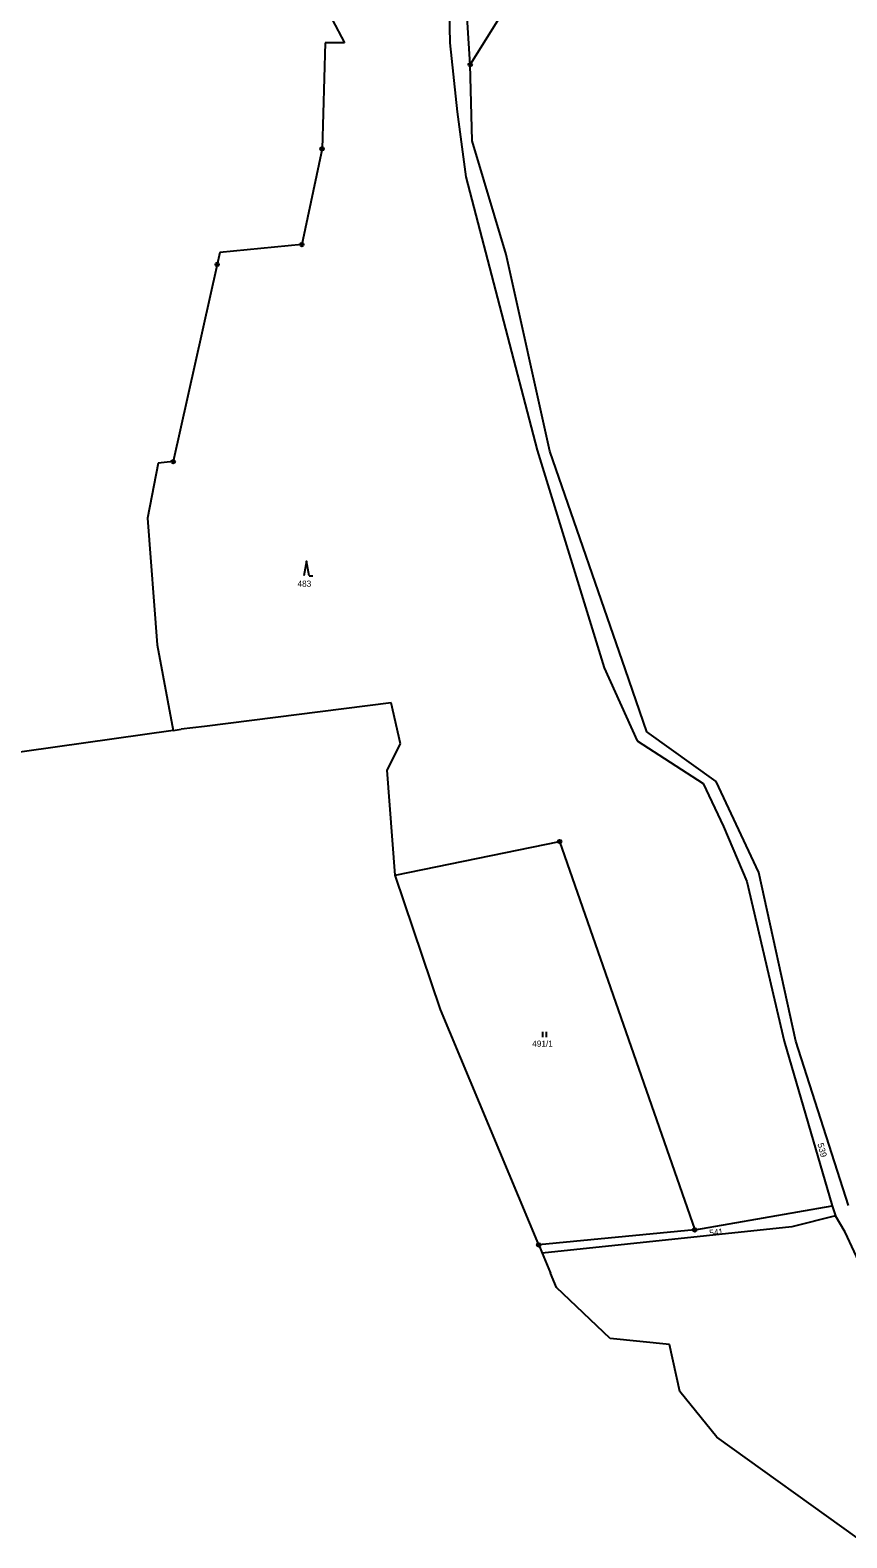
# Model space of a CAD drawing. Extents: x -885985 to -883535, y -1030025 to -1027941.
# Drawn here: x -884769.9 to -884544.6, y -1029741.6 to -1029325.6 of the extents above; entities that cross this region are included whole.
import ezdxf

# ---------------------------------------------------------------- set-up
doc = ezdxf.new("R2010")
doc.units = 0
doc.header["$LTSCALE"] = 0.68
for name, color, linetype, lineweight in [('1', 7, 'Continuous', 25), ('3', 7, 'Continuous', 25), ('8', 7, 'Continuous', 25)]:
    doc.layers.add(name, color=color, linetype=linetype, lineweight=lineweight)
doc.layers.add('2', color=7, linetype='Continuous')

msp = doc.modelspace()

# ---------------------------------------------------------------- linework, layer by layer
at = {"layer": '1'}
for p, q in [((-884648.51, -1029335.14), (-884651.18, -1029291.98)), ((-884654.72, -1029297.17), (-884654.13, -1029329.15)), ((-884693.78, -1029309.03), (-884683.21, -1029329.13)), ((-884640.06, -1029321.63), (-884648.51, -1029335.14)), ((-884688.49, -1029329.15), (-884689.38, -1029358.36)), ((-884683.21, -1029329.13), (-884688.49, -1029329.15)), ((-884654.13, -1029329.15), (-884652.07, -1029348.15)), ((-884647.96, -1029356.14), (-884648.51, -1029335.14)), ((-884652.07, -1029348.15), (-884649.72, -1029366.05)), ((-884638.56, -1029387.53), (-884647.96, -1029356.14)), ((-884689.38, -1029358.36), (-884694.96, -1029384.78)), ((-884649.72, -1029366.05), (-884630.04, -1029441.51)), ((-884694.96, -1029384.78), (-884717.58, -1029386.96)), ((-884717.58, -1029386.96), (-884718.32, -1029390.26)), ((-884626.51, -1029441.78), (-884638.56, -1029387.53)), ((-884718.32, -1029390.26), (-884730.44, -1029444.66)), ((-884630.04, -1029441.51), (-884611.53, -1029501.54)), ((-884605.66, -1029502.09), (-884626.51, -1029441.78)), ((-884734.61, -1029445.09), (-884737.55, -1029460.26)), ((-884730.44, -1029444.66), (-884734.61, -1029445.09)), ((-884737.55, -1029460.26), (-884734.9, -1029495.2)), ((-884734.9, -1029495.2), (-884730.44, -1029518.81)), ((-884611.53, -1029501.54), (-884602.43, -1029521.65)), ((-884599.78, -1029519.17), (-884605.66, -1029502.09)), ((-884670.3, -1029511.24), (-884721.82, -1029517.69)), ((-884667.73, -1029522.49), (-884670.3, -1029511.24)), ((-884721.82, -1029517.69), (-884728.27, -1029518.5)), ((-884730.44, -1029518.81), (-884879.8, -1029539.92)), ((-884730.44, -1029518.81), (-884728.27, -1029518.5)), ((-884671.4, -1029529.75), (-884667.73, -1029522.49)), ((-884602.43, -1029521.65), (-884584.21, -1029533.49)), ((-884580.69, -1029532.94), (-884599.78, -1029519.17)), ((-884669.2, -1029558.79), (-884671.4, -1029529.75)), ((-884584.21, -1029533.49), (-884578.63, -1029545.33)), ((-884568.94, -1029558), (-884580.69, -1029532.94)), ((-884578.63, -1029545.33), (-884572.17, -1029560.48)), ((-884669.2, -1029558.79), (-884623.85, -1029549.46)), ((-884623.85, -1029549.46), (-884586.56, -1029656.61)), ((-884656.72, -1029595.81), (-884669.2, -1029558.79)), ((-884558.66, -1029604.54), (-884568.94, -1029558)), ((-884572.17, -1029560.48), (-884561.89, -1029604.54)), ((-884629.61, -1029660.74), (-884656.72, -1029595.81)), ((-884561.89, -1029604.54), (-884548.67, -1029649.98)), ((-884544.19, -1029649.89), (-884558.66, -1029604.54)), ((-884586.56, -1029656.61), (-884548.67, -1029649.98)), ((-884548.67, -1029649.98), (-884547.79, -1029652.73)), ((-884547.79, -1029652.73), (-884559.83, -1029655.76)), ((-884545.05, -1029657.26), (-884547.79, -1029652.73)), ((-884586.56, -1029656.61), (-884629.61, -1029660.74)), ((-884559.83, -1029655.76), (-884628.64, -1029663.07)), ((-884525.46, -1029699.55), (-884545.05, -1029657.26)), ((-884629.61, -1029660.74), (-884628.64, -1029663.07)), ((-884628.64, -1029663.07), (-884626.34, -1029668.58)), ((-884624.75, -1029672.47), (-884626.34, -1029668.58)), ((-884609.95, -1029686.61), (-884624.75, -1029672.47)), ((-884593.52, -1029688.26), (-884609.95, -1029686.61)), ((-884590.72, -1029701.19), (-884593.52, -1029688.26)), ((-884580.46, -1029713.8), (-884590.72, -1029701.19)), ((-884541.78, -1029741.56), (-884580.46, -1029713.8))]:
    msp.add_line(p, q, dxfattribs=at)
at = {"layer": '3'}
for p, q in [((-884692.95, -1029476.16), (-884691.954, -1029476.16)), ((-884628.511, -1029603.43), (-884628.511, -1029601.93)), ((-884627.51, -1029603.43), (-884627.51, -1029601.93))]:
    msp.add_line(p, q, dxfattribs=at)
msp.add_lwpolyline([(-884692.95, -1029476.16), (-884693.7, -1029472.16), (-884694.45, -1029476.16)], dxfattribs=at)
at = {"layer": '8'}
for centre, radius in [((-884648.51, -1029335.1399), 0.5), ((-884648.51, -1029335.1399), 0.0303), ((-884689.38, -1029358.3599), 0.5), ((-884689.38, -1029358.3599), 0.0303), ((-884694.96, -1029384.7799), 0.5), ((-884694.96, -1029384.7799), 0.0303), ((-884718.32, -1029390.2599), 0.5), ((-884718.32, -1029390.2599), 0.0303), ((-884730.44, -1029444.6599), 0.5), ((-884730.44, -1029444.6599), 0.0303), ((-884623.85, -1029549.4599), 0.5), ((-884623.85, -1029549.4599), 0.0303), ((-884586.56, -1029656.6099), 0.5), ((-884586.56, -1029656.6099), 0.0303), ((-884629.61, -1029660.7399), 0.5), ((-884629.61, -1029660.7399), 0.0303)]:
    msp.add_circle(centre, radius, dxfattribs=at)

# ---------------------------------------------------------------- texts
at = {"layer": '2'}
for s, p in [('483', (-884696.16, -1029479.175)), ('491/1', (-884631.41, -1029606.075))]:
    msp.add_text(s, height=1.7, dxfattribs=at).set_placement(p)
at = {"layer": '2', "width": 1.05}
msp.add_text('539', height=1.7, rotation=285, dxfattribs=at).set_placement((-884552.75, -1029632.869))
at = {"layer": '2'}
msp.add_text('541', height=1.7, rotation=6, dxfattribs=at).set_placement((-884582.455, -1029658.292))

doc.saveas('drawing.dxf')
